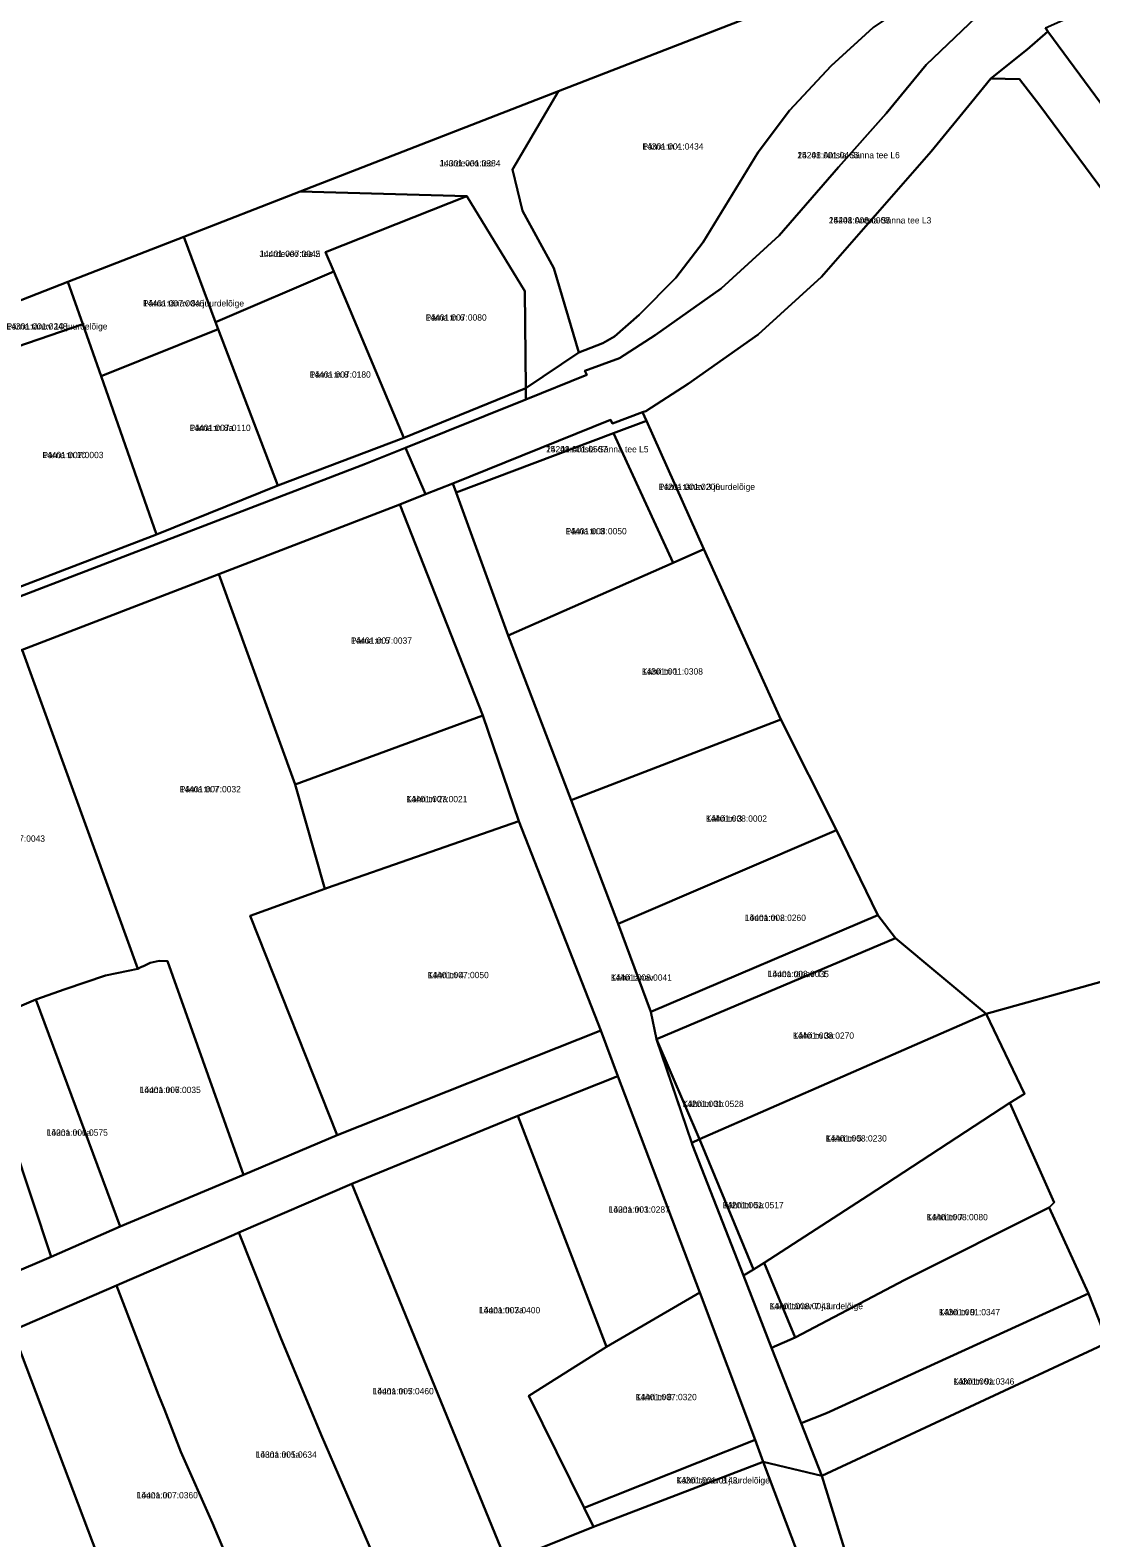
# Model space of a CAD drawing. Extents: x 640657 to 665127, y 6395726 to 6426831.
# Drawn here: x 650592.6 to 650844.3, y 6412092.9 to 6412450.8 of the extents above; entities that cross this region are included whole.
import ezdxf

# ---------------------------------------------------------------- set-up
doc = ezdxf.new("R2010")
doc.units = 0
for name, color, linetype in [('L_AADRESS', 7, 'Continuous'), ('PIIR', 7, 'Continuous'), ('TUNNUS', 7, 'Continuous')]:
    doc.layers.add(name, color=color, linetype=linetype)

msp = doc.modelspace()

# ---------------------------------------------------------------- linework, layer by layer
at = {"layer": 'PIIR'}
for points in [[(651160.5, 6412629.64), (651101.39, 6412608.29), (651093.53, 6412605.19), (651052.26, 6412589.05), (651022.22, 6412577.33), (650990.9, 6412566.44), (650951.76, 6412550.68), (650903.11, 6412531.09), (650870.55, 6412517.98), (650804.41, 6412491.35), (650795.01, 6412487.57), (650806.17, 6412470.6), (650718.02, 6412436.33), (650656.65, 6412412.46), (650629.05, 6412401.73), (650601.5, 6412391.05), (650565.08, 6412376.8)], [(650833.55, 6412451.31), (650834.15, 6412450.5), (650829.23, 6412446.2), (650820.6, 6412439.3), (650816.11, 6412433.76), (650806.43, 6412421.96), (650780.39, 6412392.27), (650765.41, 6412378.54), (650748.77, 6412366.82), (650738.74, 6412360.34), (650737.9, 6412360.1), (650730.77, 6412357.39), (650730.3, 6412358.3), (650692.9, 6412343.2), (650686.44, 6412340.63), (650681.67, 6412351.64), (650710.25, 6412363.15), (650724.72, 6412368.98), (650724.24, 6412369.89), (650732.44, 6412372.94), (650740.95, 6412378.42), (650756.61, 6412389.46), (650770.35, 6412402.07), (650784.47, 6412418.25), (650795.77, 6412431.04), (650805.23, 6412442.58), (650820.49, 6412457.13)], [(650820.49, 6412457.13), (650805.23, 6412442.58), (650795.77, 6412431.04), (650784.47, 6412418.25), (650770.35, 6412402.07), (650756.61, 6412389.46), (650740.95, 6412378.42), (650732.44, 6412372.94), (650724.24, 6412369.89), (650724.72, 6412368.98), (650710.25, 6412363.15), (650710.2, 6412365.84), (650722.8, 6412374.3), (650728.5, 6412376.5), (650731.3, 6412378.1), (650737.1, 6412383.2), (650745.8, 6412392), (650752.3, 6412400.5), (650765.4, 6412421.8), (650772.8, 6412431.7), (650782.7, 6412442.3), (650792.7, 6412451.4)], [(650847.6, 6412412.2), (650832.2, 6412432.9), (650827.4, 6412439.2), (650820.6, 6412439.3), (650829.23, 6412446.2), (650834.15, 6412450.5), (650856.7, 6412419.97)], [(650848.99, 6412225.51), (650819.46, 6412217.33), (650797.98, 6412235.23), (650793.8, 6412240.7), (650783.98, 6412260.91), (650770.75, 6412287.14), (650752.51, 6412327.6), (650738.85, 6412358.05), (650737.9, 6412360.1), (650738.74, 6412360.34), (650748.77, 6412366.82), (650765.41, 6412378.54), (650780.39, 6412392.27), (650806.43, 6412421.96), (650816.11, 6412433.76), (650820.6, 6412439.3), (650827.4, 6412439.2), (650832.2, 6412432.9), (650847.6, 6412412.2)], [(650566.91, 6412146.56), (650597.6, 6412159.62), (650613.96, 6412166.82), (650643.19, 6412179.06), (650665.48, 6412188.5), (650728.04, 6412213.38), (650732.1, 6412202.5), (650708.3, 6412193.1), (650668.93, 6412176.95), (650642.11, 6412165.39), (650640.94, 6412164.88), (650613.78, 6412153.1), (650613.09, 6412152.8), (650588.4, 6412142.1)], [(650805.4, 6411759.6), (650823.8, 6411856.1), (650826.8, 6411883.9), (650826.9, 6411904.1), (650826.36, 6411915.13), (650824.35, 6411932.36), (650820.5, 6411947.6), (650789.4, 6412050.4), (650766.59, 6412110.96), (650780.5, 6412107.64), (650834.4, 6411933.05), (650837.65, 6411902.83), (650837.42, 6411887.72), (650834.9, 6411868.4), (650833.54, 6411856.63), (650829.02, 6411827.83), (650823.72, 6411798.98)]]:
    msp.add_lwpolyline(points, dxfattribs=at)
for points in [[(650806.17, 6412470.6), (650812.5, 6412464.2), (650807.4, 6412460.7), (650800.1, 6412456.4), (650792.7, 6412451.4), (650782.7, 6412442.3), (650772.8, 6412431.7), (650765.4, 6412421.8), (650752.3, 6412400.5), (650745.8, 6412392), (650737.1, 6412383.2), (650731.3, 6412378.1), (650728.5, 6412376.5), (650722.8, 6412374.3), (650716.9, 6412394.3), (650709.4, 6412407.9), (650707.1, 6412417.7), (650718.02, 6412436.33)], [(650833.55, 6412451.31), (650847.46, 6412457.49), (650886.48, 6412455.5), (650893.8, 6412421.45), (650856.7, 6412419.97), (650834.15, 6412450.5)], [(650656.65, 6412412.46), (650718.02, 6412436.33), (650707.1, 6412417.7), (650709.4, 6412407.9), (650716.9, 6412394.3), (650722.8, 6412374.3), (650710.2, 6412365.84), (650709.96, 6412388.8), (650696.25, 6412411.4)], [(650629.05, 6412401.73), (650656.65, 6412412.46), (650696.25, 6412411.4), (650662.65, 6412398.13), (650664.64, 6412393.48), (650636.56, 6412381.45)], [(650681.27, 6412354.05), (650664.64, 6412393.48), (650662.65, 6412398.13), (650696.25, 6412411.4), (650709.96, 6412388.8), (650710.2, 6412365.84)], [(650601.5, 6412391.05), (650629.05, 6412401.73), (650636.56, 6412381.45), (650637.17, 6412379.79), (650609.43, 6412368.68), (650605.06, 6412381.02)], [(650565.08, 6412376.8), (650601.5, 6412391.05), (650605.06, 6412381.02), (650568.36, 6412368.42)], [(650651.4, 6412342.72), (650637.17, 6412379.79), (650636.56, 6412381.45), (650664.64, 6412393.48), (650681.27, 6412354.05)], [(650622.59, 6412331.04), (650588.1, 6412317.86), (650568.36, 6412368.42), (650605.06, 6412381.02), (650609.43, 6412368.68)], [(650609.43, 6412368.68), (650637.17, 6412379.79), (650651.4, 6412342.72), (650622.59, 6412331.04)], [(650681.67, 6412351.64), (650672.2, 6412347.82), (650586.41, 6412314.93), (650510.41, 6412286.19), (650444.15, 6412260.45), (650404.62, 6412244.86), (650403.6, 6412247.5), (650449.18, 6412265.33), (650471.83, 6412273.72), (650494.34, 6412282.16), (650519.44, 6412292.01), (650539.66, 6412299.23), (650584.5, 6412316.46), (650588.1, 6412317.86), (650622.59, 6412331.04), (650651.4, 6412342.72), (650681.27, 6412354.05), (650710.2, 6412365.84), (650710.25, 6412363.15)], [(650693.66, 6412341.04), (650692.9, 6412343.2), (650730.3, 6412358.3), (650730.77, 6412357.39), (650737.9, 6412360.1), (650738.85, 6412358.05), (650731.02, 6412355.13)], [(650745.17, 6412324.37), (650706.02, 6412307.12), (650693.66, 6412341.04), (650731.02, 6412355.13)], [(650731.02, 6412355.13), (650738.85, 6412358.05), (650752.51, 6412327.6), (650745.17, 6412324.37)], [(650404.91, 6412232.08), (650400.69, 6412243.34), (650404.62, 6412244.86), (650444.15, 6412260.45), (650510.41, 6412286.19), (650586.41, 6412314.93), (650672.2, 6412347.82), (650681.67, 6412351.64), (650686.44, 6412340.63), (650680.3, 6412338.2), (650637.4, 6412321.7), (650590.69, 6412303.71), (650545.1, 6412286.4), (650514.71, 6412274.99), (650503.73, 6412270.7), (650498.13, 6412268.54), (650452.2, 6412250.7), (650448.47, 6412249.25)], [(650700, 6412288.1), (650680.3, 6412338.2), (650686.44, 6412340.63), (650692.9, 6412343.2), (650693.66, 6412341.04), (650706.02, 6412307.12), (650721.02, 6412268.04), (650732.15, 6412238.65), (650739.89, 6412217.8), (650741.24, 6412211.32), (650749.8, 6412186.1), (650761.93, 6412155.22), (650768.55, 6412138.01), (650775.61, 6412120.12), (650780.5, 6412107.64), (650766.59, 6412110.96), (650764.64, 6412116.15), (650751.5, 6412151.18), (650732.1, 6412202.5), (650728.04, 6412213.38), (650708.59, 6412263.01)], [(650637.4, 6412321.7), (650680.3, 6412338.2), (650700, 6412288.1), (650655.5, 6412271.7)], [(650721.02, 6412268.04), (650706.02, 6412307.12), (650745.17, 6412324.37), (650752.51, 6412327.6), (650770.75, 6412287.14)], [(650637.4, 6412321.7), (650655.5, 6412271.7), (650662.53, 6412246.96), (650644.8, 6412240.55), (650665.48, 6412188.5), (650643.19, 6412179.06), (650625.19, 6412229.81), (650623.19, 6412229.86), (650621.08, 6412229.42), (650619.46, 6412228.65), (650618.97, 6412228.42), (650618.1, 6412228), (650590.69, 6412303.71)], [(650545.1, 6412286.4), (650590.69, 6412303.71), (650618.1, 6412228), (650615.84, 6412227.48), (650610.43, 6412226.37), (650600.88, 6412223.19), (650593.95, 6412220.71), (650583.45, 6412216.26), (650579.06, 6412215.74), (650579.16, 6412215.03), (650571.83, 6412212.28)], [(650700, 6412288.1), (650708.59, 6412263.01), (650663.19, 6412247.2), (650662.53, 6412246.96), (650655.5, 6412271.7)], [(650770.75, 6412287.14), (650783.98, 6412260.91), (650732.15, 6412238.65), (650721.02, 6412268.04)], [(650997.08, 6412212.14), (650983.04, 6412206.16), (650848.37, 6412139.28), (650843.75, 6412150.93), (650834.44, 6412171.36), (650835.66, 6412172.48), (650825.12, 6412196.14), (650828.58, 6412198.31), (650819.46, 6412217.33), (650848.99, 6412225.51), (650885.41, 6412239.63), (650921.7, 6412253.31), (650950.03, 6412273.09), (650951.64, 6412281.64), (650960.19, 6412274.16), (650970.35, 6412259.19), (650985.32, 6412234.06)], [(650663.19, 6412247.2), (650708.59, 6412263.01), (650728.04, 6412213.38), (650665.48, 6412188.5), (650644.8, 6412240.55), (650662.53, 6412246.96)], [(650732.15, 6412238.65), (650783.98, 6412260.91), (650793.8, 6412240.7), (650739.89, 6412217.8)], [(650739.89, 6412217.8), (650793.8, 6412240.7), (650797.98, 6412235.23), (650741.24, 6412211.32)], [(650741.24, 6412211.32), (650797.98, 6412235.23), (650819.46, 6412217.33), (650751.46, 6412187.53)], [(650600.88, 6412223.19), (650610.43, 6412226.37), (650615.84, 6412227.48), (650618.1, 6412228), (650618.97, 6412228.42), (650619.46, 6412228.65), (650621.08, 6412229.42), (650623.19, 6412229.86), (650625.19, 6412229.81), (650643.19, 6412179.06), (650613.96, 6412166.82), (650593.95, 6412220.71)], [(650583.45, 6412216.26), (650593.95, 6412220.71), (650613.96, 6412166.82), (650597.6, 6412159.62), (650579.16, 6412215.03), (650579.06, 6412215.74)], [(650819.46, 6412217.33), (650828.58, 6412198.31), (650825.12, 6412196.14), (650791.49, 6412174.15), (650766.76, 6412158.2), (650764.24, 6412156.64), (650751.46, 6412187.53)], [(650579.16, 6412215.03), (650597.6, 6412159.62), (650566.91, 6412146.56), (650547.48, 6412203.15), (650571.83, 6412212.28)], [(650751.46, 6412187.53), (650749.6, 6412186.69), (650741.24, 6412211.32)], [(650983.04, 6412206.16), (651013.66, 6412146.38), (651035.34, 6412103.54), (651075.36, 6412025.23), (651049.71, 6412021.34), (651050.96, 6411983.58), (650908.42, 6411918.41), (650898.06, 6411957.13), (650834.4, 6411933.05), (650780.5, 6412107.64), (650848.37, 6412139.28)], [(650708.3, 6412193.1), (650732.1, 6412202.5), (650751.5, 6412151.18), (650729.36, 6412138.25)], [(650774.19, 6412140.46), (650766.76, 6412158.2), (650791.49, 6412174.15), (650825.12, 6412196.14), (650835.66, 6412172.48), (650834.44, 6412171.36), (650800.21, 6412154.17)], [(650710.98, 6412126.63), (650724.07, 6412100), (650726.28, 6412095.5), (650705.63, 6412087.23), (650668.93, 6412176.95), (650708.3, 6412193.1), (650729.36, 6412138.25)], [(650749.6, 6412186.69), (650751.46, 6412187.53), (650764.24, 6412156.64), (650761.93, 6412155.22), (650749.8, 6412186.1)], [(650679.11, 6412076.99), (650661.62, 6412117.39), (650652.01, 6412140.52), (650642.11, 6412165.39), (650668.93, 6412176.95), (650705.63, 6412087.23)], [(650775.61, 6412120.12), (650768.55, 6412138.01), (650774.16, 6412140.47), (650800.21, 6412154.17), (650834.44, 6412171.36), (650843.75, 6412150.93), (650781.62, 6412122.52)], [(650623.04, 6412126.86), (650613.09, 6412152.8), (650613.78, 6412153.1), (650640.94, 6412164.88), (650642.11, 6412165.39), (650652.01, 6412140.52), (650661.62, 6412117.39), (650679.11, 6412076.99), (650647.36, 6412064.42), (650642, 6412081.75), (650635.83, 6412096.43), (650628.36, 6412113.34), (650624.44, 6412123.39)], [(650761.93, 6412155.22), (650764.24, 6412156.64), (650766.76, 6412158.2), (650774.19, 6412140.46), (650768.55, 6412138.01)], [(650628.36, 6412113.34), (650635.83, 6412096.43), (650642, 6412081.75), (650647.36, 6412064.42), (650621.89, 6412053.65), (650588.4, 6412142.1), (650613.09, 6412152.8), (650623.04, 6412126.86), (650624.44, 6412123.39)], [(650724.07, 6412100), (650710.98, 6412126.63), (650729.36, 6412138.25), (650751.5, 6412151.18), (650764.64, 6412116.15)], [(650780.5, 6412107.64), (650775.61, 6412120.12), (650781.62, 6412122.52), (650843.75, 6412150.93), (650848.37, 6412139.28)], [(650567.01, 6412133.18), (650588.4, 6412142.1), (650621.89, 6412053.65), (650596.67, 6412043.32)], [(650726.28, 6412095.5), (650724.07, 6412100), (650764.64, 6412116.15), (650766.59, 6412110.96)], [(650596.67, 6412043.32), (650621.89, 6412053.65), (650647.36, 6412064.42), (650679.11, 6412076.99), (650705.63, 6412087.23), (650726.28, 6412095.5), (650766.59, 6412110.96), (650789.4, 6412050.4), (650668.08, 6411995.9), (650711.9, 6411895), (650820.5, 6411947.6), (650824.35, 6411932.36), (650826.36, 6411915.13), (650826.9, 6411904.1), (650826.8, 6411883.9), (650823.8, 6411856.1), (650805.4, 6411759.6), (650796.5, 6411717.4), (650773.8, 6411644.8), (650770.94, 6411634.37), (650770.03, 6411622.67)]]:
    msp.add_lwpolyline(points, close=True, dxfattribs=at)

# ---------------------------------------------------------------- texts
at = {"layer": 'L_AADRESS'}
for s, p in [('Pärna tn 4', (650737.89, 6412422.45)), ('Juurdeveo tee', (650689.72, 6412418.45)), ('25248 Antsla-Sänna tee L6', (650774.68, 6412420.37)), ('25248 Antsla-Sänna tee L3', (650782.15, 6412404.91)), ('Juurdeveo tee 2', (650646.99, 6412396.96)), ('Pärna tänav 8a juurdelõige', (650619.37, 6412385.21)), ('Pärna tänav 10 juurdelõige', (650586.95, 6412379.74)), ('Pärna tn 6', (650686.43, 6412381.84)), ('Pärna tn 8', (650658.92, 6412368.3)), ('Pärna tn 8a', (650630.41, 6412355.65)), ('25248 Antsla-Sänna tee L5', (650715.04, 6412350.57)), ('Pärna tn 10', (650595.48, 6412349.2)), ('Pärna tänav 3 juurdelõige', (650741.77, 6412341.66)), ('Pärna tn 3', (650719.67, 6412331.12)), ('Pärna tn 5', (650668.7, 6412305.15)), ('Kähri tn 1', (650737.76, 6412297.82)), ('Pärna tn 7', (650628.08, 6412269.88)), ('Kähri tn 2a', (650681.86, 6412267.53)), ('Kähri tn 3', (650752.97, 6412262.9)), ('Lõuna tn 2', (650762.21, 6412239.36)), ('Kähri tn 4', (650686.93, 6412225.76)), ('Kähri tänav', (650730.4, 6412225.16)), ('Lõuna tänav T1', (650767.66, 6412226.01)), ('Kähri tn 3a', (650773.63, 6412211.38)), ('Lõuna tn 6', (650618.57, 6412198.49)), ('Kähri tn 3b', (650747.43, 6412195.18)), ('Lõuna tn 6a', (650596.51, 6412188.36)), ('Kähri tn 5', (650781.4, 6412186.99)), ('Kähri tn 5a', (650756.92, 6412171.15)), ('Lõuna tn 3', (650729.9, 6412170.1)), ('Kähri tn 7', (650805.38, 6412168.3)), ('Lõuna tn 3a', (650699.14, 6412146.21)), ('Kähri tänav 7 juurdelõige', (650768.06, 6412147.19)), ('Kähri tn 9', (650808.29, 6412145.74)), ('Kähri tn 9a', (650811.67, 6412129.29)), ('Lõuna tn 5', (650673.87, 6412126.98)), ('Kähri tn 8', (650736.3, 6412125.59)), ('Lõuna tn 5a', (650646.1, 6412111.93)), ('Kähri tänav 8 juurdelõige', (650745.95, 6412105.82)), ('Lõuna tn 7', (650617.88, 6412102.28))]:
    msp.add_text(s, height=1.5, dxfattribs=at).set_placement(p)
at = {"layer": 'TUNNUS'}
for s, p in [('14301:001:0434', (650737.89, 6412422.45)), ('14301:001:0384', (650689.72, 6412418.45)), ('14201:001:0465', (650774.68, 6412420.37)), ('14401:008:0008', (650782.15, 6412404.91)), ('14401:007:0045', (650646.99, 6412396.96)), ('14401:007:0046', (650619.37, 6412385.21)), ('14301:001:0248', (650586.95, 6412379.74)), ('14401:007:0080', (650686.43, 6412381.84)), ('14401:007:0180', (650658.92, 6412368.3)), ('14401:007:0110', (650630.41, 6412355.65)), ('14201:001:0507', (650715.04, 6412350.57)), ('14401:007:0003', (650595.48, 6412349.2)), ('14201:001:0206', (650741.77, 6412341.66)), ('14401:008:0050', (650719.67, 6412331.12)), ('14401:007:0037', (650668.7, 6412305.15)), ('14301:001:0308', (650737.76, 6412297.82)), ('14401:007:0032', (650628.08, 6412269.88)), ('14401:007:0021', (650681.86, 6412267.53)), ('14401:008:0002', (650752.97, 6412262.9)), ('14401:007:0043', (650581.6, 6412258.15)), ('14401:008:0260', (650762.21, 6412239.36)), ('14401:007:0050', (650686.93, 6412225.76)), ('14401:008:0041', (650730.4, 6412225.16)), ('14401:008:0035', (650767.66, 6412226.01)), ('14401:008:0270', (650773.63, 6412211.38)), ('14401:007:0035', (650618.57, 6412198.49)), ('14201:001:0528', (650747.43, 6412195.18)), ('14201:001:0575', (650596.51, 6412188.36)), ('14401:008:0230', (650781.4, 6412186.99)), ('14201:001:0517', (650756.92, 6412171.15)), ('14201:001:0287', (650729.9, 6412170.1)), ('14401:008:0080', (650805.38, 6412168.3)), ('14401:007:0400', (650699.14, 6412146.21)), ('14401:008:0043', (650768.06, 6412147.19)), ('14301:001:0347', (650808.29, 6412145.74)), ('14301:001:0346', (650811.67, 6412129.29)), ('14401:007:0460', (650673.87, 6412126.98)), ('14401:007:0320', (650736.3, 6412125.59)), ('14301:001:0634', (650646.1, 6412111.93)), ('14301:001:0143', (650745.95, 6412105.82)), ('14401:007:0360', (650617.88, 6412102.28))]:
    msp.add_text(s, height=1.5, dxfattribs=at).set_placement(p)

doc.saveas('drawing.dxf')
